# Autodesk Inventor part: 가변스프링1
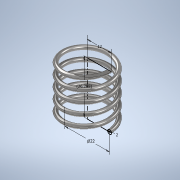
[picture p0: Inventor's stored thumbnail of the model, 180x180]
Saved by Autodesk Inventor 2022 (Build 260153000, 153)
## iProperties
Created: 2021-07
Part Number: 가변스프링1
Material: 강철, 연강
Document SubType Name: Modeling
Designer: micke
Density: 7.85 g/cm^3
Appearance: 반연마
Mass: 8.38384 g
Surface Area: 21.6617 cm^2
Volume: 1.068 cm^3
Author: micke
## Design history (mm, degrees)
sketch "스케치1"
  geometry: L1 (0, 0)-(0, 26.208); L2 (0, 26.208)-(12, 26.208); L3 (0, 0)-(11, 0); C1 r 1 at (11, 0)
  constraints: 6 end point, 2 horizontal, 1 centre point, 1 coincident, 1 vertical
  dimensions: "d0" = 26.20829 distance of L1.start L1.end (derived); "d1" = 2 diameter of C1; "d2" = 22 diameter of L3.end L1; "d3" = 12 distance of L1.end L2.end
feature "코일1" sketch "스케치1" pitch "d4" = 10; turns "d6" = 5; dims "d5" = 26.20829 (= d0), "d7" = 0, angle "d8" = 90 deg, angle "d9" = 90 deg, "d10" = 0, "d11" = 0
sketch "스케치2"
  geometry: L1 (26.208, 12.5)-(0, 12.5); L2 (0, 12.5)-(0, -12.5); L3 (0, -12.5)-(26.208, -12.5); L4 (26.208, -12.5)-(26.208, 12.5); 2 further points
  constraints: 8 end point, 2 parallel, 1 coincident, 1 horizontal, 1 midpoint, 1 perpendicular
  dimensions: "d12" = 26.20829 distance of L1.start L1.end (= d0); "d13" = 25 distance of L3.end L1.start
extrude "돌출1" sketch "스케치2" extent not by distance; stored distance "d14" = 0; taper "d15" = 0 deg
node "솔리드1"
feature "A9D066F2-1C7D-4E18-AEED-F7BC21143FA4" dims "d4" = 10, "d5" = 26.20829 (= d0), "d6" = 50, "d7" = 0, "d8" = 90 deg, "d9" = 90 deg, "d10" = 0, "d11" = 0
